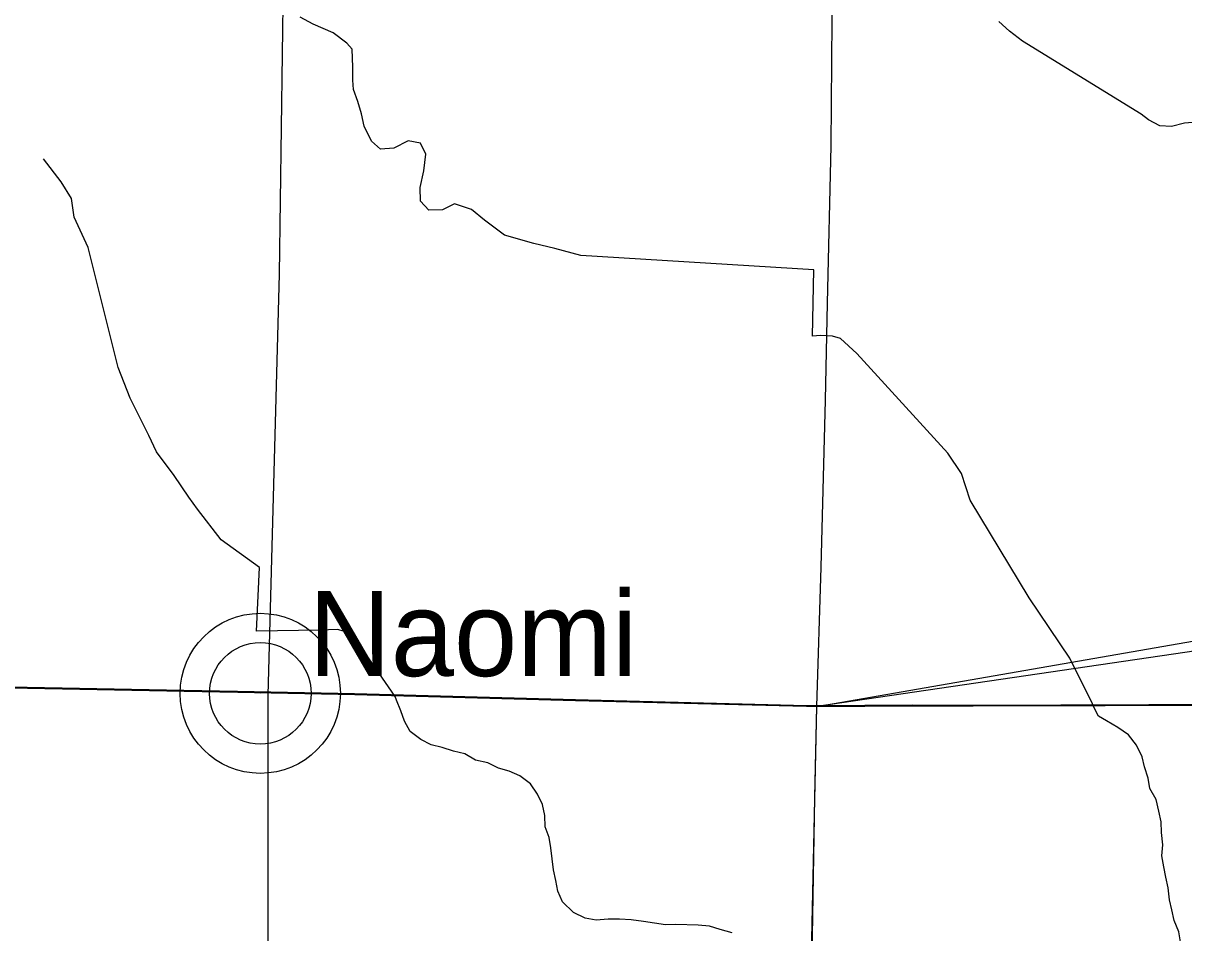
# Model space of a CAD drawing. Extents: x -6.2 to 37.4, y 0.2 to 22.2.
# Drawn here: x 2.101 to 2.64, y 20.275 to 20.698 of the extents above; entities that cross this region are included whole.
import ezdxf

# ---------------------------------------------------------------- set-up
doc = ezdxf.new("R2010")
doc.units = 0
for name, color, linetype in [('GM_X_County_Road', 7, 'Continuous'), ('GM_X_Minor_River', 7, 'Continuous'), ('GM_X_Rail_Line', 7, 'Continuous'), ('GM_X_State_Route', 7, 'Continuous'), ('GM_X_Unincorporated', 7, 'Continuous'), ('GM_X_Unincorporated_Location', 7, 'Continuous'), ('GM_X_Unincorporated_Text', 7, 'Continuous'), ('SH_Border', 7, 'Continuous'), ('SH_Cut_Line', 7, 'Continuous'), ('SH_Data', 7, 'Continuous')]:
    doc.layers.add(name, color=color, linetype=linetype)

msp = doc.modelspace()

# ---------------------------------------------------------------- linework, layer by layer
at = {"layer": 'GM_X_County_Road'}
for points in [[(1.96666, 20.39186), (2.02154, 20.39069), (2.09459, 20.38911), (2.17541, 20.38757), (2.20027, 20.38703), (2.25468, 20.38592), (2.35724, 20.3832), (2.46447, 20.38049), (2.46928, 20.38039)], [(2.46928, 20.38039), (2.51395, 20.38066), (2.54189, 20.38062), (2.66452, 20.38098), (2.72507, 20.38108), (2.80889, 20.38049), (2.85856, 20.38021), (2.97166, 20.37909)]]:
    msp.add_lwpolyline(points, dxfattribs=at)
at = {"layer": 'GM_X_Minor_River'}
for points in [[(2.59727, 20.38156), (2.58677, 20.40288), (2.56793, 20.43085), (2.54043, 20.47629), (2.53638, 20.48872), (2.53017, 20.49817), (2.48789, 20.54435), (2.48029, 20.55136), (2.47652, 20.5524), (2.47102, 20.55272), (2.46722, 20.55243), (2.46781, 20.58335), (2.35966, 20.58993), (2.34761, 20.59326), (2.3378, 20.59558), (2.32424, 20.59933), (2.31493, 20.60638), (2.30879, 20.61127), (2.3009, 20.61393), (2.29533, 20.61122), (2.28906, 20.61099), (2.28518, 20.61525), (2.28496, 20.62152), (2.28667, 20.62926), (2.28763, 20.63702), (2.2851, 20.6422), (2.27944, 20.64329), (2.27271, 20.63984), (2.26663, 20.63942), (2.26236, 20.64313), (2.25893, 20.65004), (2.25775, 20.65576), (2.25599, 20.6615), (2.25405, 20.66705), (2.25378, 20.67142), (2.25374, 20.67749), (2.25338, 20.68585), (2.25098, 20.68856), (2.24465, 20.69346), (2.23527, 20.69748), (2.22928, 20.70066)], [(2.56474, 20.68955), (2.55879, 20.69425), (2.55378, 20.69874)], [(2.61985, 20.65559), (2.56474, 20.68955)], [(2.71283, 20.62679), (2.70821, 20.63164), (2.70336, 20.6348), (2.69811, 20.63758), (2.69231, 20.64038), (2.68756, 20.6403), (2.68261, 20.63966), (2.67741, 20.64415), (2.67237, 20.64712), (2.66751, 20.64989), (2.6626, 20.65077), (2.65786, 20.65088), (2.65198, 20.65121), (2.64574, 20.65193), (2.64004, 20.6515), (2.63393, 20.64994), (2.62863, 20.65026), (2.62339, 20.65304), (2.61985, 20.65559)], [(2.27341, 20.38497), (2.25688, 20.40911), (2.25265, 20.41452), (2.24662, 20.41619), (2.23827, 20.41582), (2.20904, 20.41538), (2.21036, 20.44495), (2.19266, 20.4579), (2.18163, 20.47202), (2.1776, 20.47762), (2.17083, 20.48765), (2.16257, 20.49866), (2.15897, 20.50634), (2.1503, 20.52362), (2.14478, 20.53799), (2.13081, 20.59373), (2.12433, 20.60774), (2.12304, 20.6165), (2.1183, 20.6242), (2.11003, 20.63484)], [(2.27406, 20.38339), (2.27341, 20.38497)], [(2.43, 20.2752), (2.42435, 20.2767), (2.41947, 20.27837), (2.41417, 20.27872), (2.40375, 20.27904), (2.399, 20.27899), (2.38881, 20.28044), (2.38295, 20.28119), (2.37765, 20.28154), (2.37233, 20.28152), (2.36682, 20.28112), (2.36173, 20.28203), (2.35631, 20.28466), (2.35115, 20.28957), (2.34903, 20.29456), (2.34805, 20.29953), (2.34688, 20.3045), (2.34569, 20.31478), (2.34489, 20.31955), (2.34315, 20.32454), (2.34294, 20.32967), (2.34177, 20.33483), (2.33946, 20.33964), (2.3362, 20.34449), (2.33138, 20.34824), (2.32633, 20.35029), (2.32144, 20.35177), (2.3164, 20.3542), (2.31074, 20.35551), (2.30571, 20.35832), (2.30044, 20.35962), (2.29518, 20.3613), (2.2901, 20.36259), (2.28525, 20.36502), (2.28043, 20.36877), (2.27774, 20.3736), (2.27599, 20.3784), (2.27406, 20.38339)], [(2.6385, 20.2692), (2.63737, 20.27568), (2.63526, 20.28087), (2.63409, 20.28584), (2.6331, 20.29062), (2.63252, 20.29614), (2.63135, 20.30111), (2.63036, 20.30588), (2.62958, 20.31103), (2.62993, 20.31614), (2.62935, 20.32185), (2.62913, 20.32679), (2.62815, 20.33176), (2.6268, 20.33711), (2.62393, 20.34232), (2.62313, 20.34709), (2.6214, 20.35227), (2.62041, 20.35704), (2.61774, 20.36244), (2.6141, 20.36729), (2.60908, 20.37067), (2.60386, 20.37368), (2.60006, 20.37596), (2.59829, 20.3794), (2.59727, 20.38156)]]:
    msp.add_lwpolyline(points, dxfattribs=at)
at = {"layer": 'GM_X_Rail_Line'}
for points in [[(2.21442, 20.38558), (2.21964, 20.58135), (2.22392, 20.88811), (2.22764, 21.10742)], [(2.09447, 20.38938), (2.17529, 20.38784), (2.20016, 20.38731), (2.25456, 20.3862), (2.35713, 20.38348), (2.46436, 20.38077), (2.46916, 20.38066), (2.51383, 20.38094), (2.54177, 20.38089), (2.66441, 20.38125)], [(2.96378, 20.16572), (2.97168, 20.36934), (2.97154, 20.37937), (2.85845, 20.38049), (2.80877, 20.38077), (2.72495, 20.38136), (2.66441, 20.38125), (2.54177, 20.38089), (2.51383, 20.38094), (2.46916, 20.38066), (2.46436, 20.38077), (2.35713, 20.38348), (2.25456, 20.3862), (2.20016, 20.38731), (2.17529, 20.38784), (2.09447, 20.38938)], [(2.1878, 18.27967), (2.17736, 18.30787), (2.17266, 18.33503), (2.17214, 18.35383), (2.17266, 18.36637), (2.17266, 18.39771), (2.17631, 18.48231), (2.18989, 18.88081), (2.19563, 19.20723), (2.19928, 19.38429), (2.20607, 19.88567), (2.21442, 20.17554), (2.21442, 20.38558)]]:
    msp.add_lwpolyline(points, dxfattribs=at)
at = {"layer": 'GM_X_State_Route'}
for points in [[(2.46928, 20.38039), (2.47126, 20.44507), (2.47327, 20.52276), (2.47424, 20.56782), (2.47587, 20.64086), (2.47707, 20.77764), (2.47815, 20.88427), (2.47827, 20.89732), (2.48298, 21.10554), (2.48299, 21.10742)], [(2.43212, 18.433), (2.43414, 18.53139), (2.43675, 18.63684), (2.43805, 18.72174), (2.44066, 18.8149), (2.44197, 18.87643), (2.44392, 18.95481), (2.4461, 19.03635), (2.44794, 19.11331), (2.44805, 19.12745), (2.45055, 19.22876), (2.45121, 19.28594), (2.45305, 19.3677), (2.45327, 19.37791), (2.45632, 19.54141), (2.45892, 19.71861), (2.46045, 19.82428), (2.46077, 19.8795), (2.4636, 20.0667), (2.46621, 20.23629), (2.46928, 20.38039)]]:
    msp.add_lwpolyline(points, dxfattribs=at)
at = {"layer": 'GM_X_Unincorporated'}
for radius in [0.0372, 0.02358]:
    msp.add_circle((2.21077, 20.3865), radius, dxfattribs=at)
at = {"layer": 'GM_X_Unincorporated_Location'}
msp.add_line((2.21077, 20.3865), (2.21077, 20.3865), dxfattribs=at)
at = {"layer": 'SH_Border'}
for p, q in [((2.46928, 20.38039), (9.08657, 21.53204)), ((9.08657, 21.35383), (2.46928, 20.38039))]:
    msp.add_line(p, q, dxfattribs=at)
at = {"layer": 'SH_Cut_Line'}
for points in [[(3.19571, 20.36573), (3.07912, 20.36764), (3.02005, 20.36861), (2.98118, 20.3693), (2.97387, 20.36928), (2.97168, 20.36934), (2.97154, 20.37937), (2.85845, 20.38049), (2.80877, 20.38077), (2.72495, 20.38136), (2.66441, 20.38125), (2.54177, 20.38089), (2.51383, 20.38094), (2.46916, 20.38066), (2.46436, 20.38077), (2.35713, 20.38348), (2.25456, 20.3862), (2.20016, 20.38731), (2.17529, 20.38784), (2.09447, 20.38938)], [(2.09447, 20.38938), (2.17529, 20.38784), (2.20016, 20.38731), (2.25456, 20.3862), (2.35713, 20.38348), (2.46436, 20.38077), (2.46916, 20.38066), (2.51383, 20.38094), (2.54177, 20.38089), (2.66441, 20.38125), (2.72495, 20.38136), (2.80877, 20.38077), (2.85845, 20.38049), (2.97154, 20.37937), (2.97168, 20.36934), (2.97387, 20.36928), (2.98118, 20.3693), (3.02005, 20.36861), (3.07912, 20.36764), (3.19571, 20.36573)]]:
    msp.add_lwpolyline(points, dxfattribs=at)
at = {"layer": 'SH_Data'}
msp.add_lwpolyline([(9.08657, 21.35383), (2.46928, 20.38039), (9.08657, 21.53204)], close=True, dxfattribs=at)
msp.add_lwpolyline([(2.48033, 17.82715), (2.48152, 17.88676), (2.48721, 18.16699), (2.48636, 18.21827), (2.47679, 18.25616), (2.46542, 18.28173), (2.44933, 18.31438), (2.4371, 18.34596), (2.43149, 18.38016), (2.432, 18.42716), (2.43323, 18.48705), (2.438, 18.71824), (2.44593, 19.03008), (2.45189, 19.31604), (2.46228, 19.97933), (2.46838, 20.33827), (2.46928, 20.38039)], dxfattribs=at)

# ---------------------------------------------------------------- texts
at = {"layer": 'GM_X_Unincorporated_Text'}
msp.add_text('Naomi', height=0.039489, rotation=0, dxfattribs=at).set_placement((2.23324, 20.39453))

doc.saveas('drawing.dxf')
